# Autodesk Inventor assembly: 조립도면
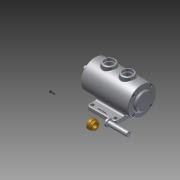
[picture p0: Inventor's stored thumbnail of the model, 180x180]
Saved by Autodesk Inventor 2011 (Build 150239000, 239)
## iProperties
Created: 2014-12
Part Number: 조립도면
Document SubType Name: Assembly
Designer: user
Author: user
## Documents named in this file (10)
- D:\441225V1003\조립도면.iam
- D:\441225V1003\1.본체.ipt
- D:\441225V1003\2.축.ipt
- D:\441225V1003\뒷커버.ipt
- D:\441225V1003\베어링 6203.ipt
- D:\441225V1003\부시.ipt
- D:\441225V1003\슬라이더.ipt
- D:\441225V1003\앞커버.ipt
- D:\441225V1003\오일실.ipt
- D:\441225V1003\M4-소켓머리.ipt
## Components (14 placed, 5 different names)
1. 1.본체:1
2. 2.축:1
3. 7-베어링 6203:1
4. 8-오일실:1
5. 9-M4-소켓머리:1
6. 7-베어링 6203:2
7. 9-M4-소켓머리:2
8. 9-M4-소켓머리:4
9. 9-M4-소켓머리:5
10. 9-M4-소켓머리:6
11. 9-M4-소켓머리:3
12. 9-M4-소켓머리:7
13. 9-M4-소켓머리:8
14. 9-M4-소켓머리:9
